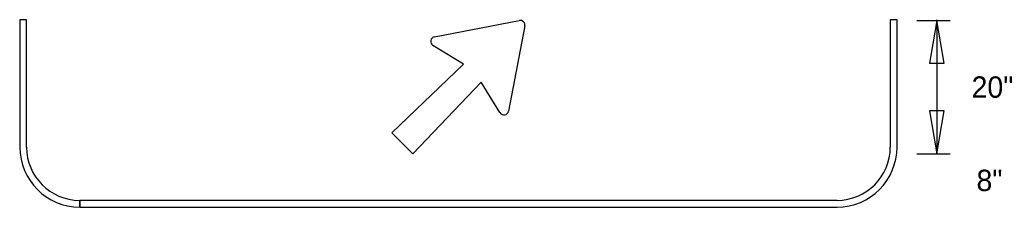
# Model space of a CAD drawing. Extents: x 0 to 770, y 0 to 495.
# Drawn here: x 564.2 to 727.2, y 238.5 to 269.1 of the extents above; entities that cross this region are included whole.
import ezdxf

# ---------------------------------------------------------------- set-up
doc = ezdxf.new("R2010")
doc.units = 0
for name, color, linetype in [('Default', 7, 'Continuous'), ('Dimension', 7, 'Continuous'), ('GSBWFill', 7, 'Continuous'), ('GSColorFill', 7, 'Continuous'), ('GSDims', 7, 'Continuous'), ('GSOutline', 7, 'Continuous')]:
    doc.layers.add(name, color=color, linetype=linetype)

msp = doc.modelspace()

# ---------------------------------------------------------------- linework, layer by layer
at = {"layer": 'Dimension'}
for points in [[(714.87, 269.05), (713.68, 262.04), (716.06, 262.04)], [(714.87, 247.19), (716.06, 254.21), (713.68, 254.21)]]:
    msp.add_lwpolyline(points, close=True, dxfattribs=at)
at = {"layer": 'GSBWFill'}
for p, q in [((564.19, 269.13), (564.19, 248.29)), ((564.19, 269.13), (564.19, 248.29)), ((565.28, 248.29), (565.28, 269.13)), ((632.33, 266.36), (646.26, 269.04)), ((707.22, 269.13), (707.22, 248.29)), ((708.32, 248.29), (708.32, 269.13)), ((708.32, 248.29), (708.32, 269.13)), ((647.17, 268.14), (644.49, 254.2)), ((644.49, 254.2), (644.49, 254.2)), ((574.02, 238.46), (574.02, 239.55)), ((574.02, 238.46), (698.49, 238.46)), ((698.49, 239.55), (574.03, 239.55)), ((574.03, 239.55), (574.03, 238.46)), ((574.03, 238.46), (698.49, 238.46))]:
    msp.add_line(p, q, dxfattribs=at)
for points in [[(565.28, 269.13), (564.19, 269.13)], [(708.32, 269.13), (707.22, 269.13)], [(643.07, 253.94), (640.01, 258.93), (628.75, 247.19), (625.32, 250.62), (637.06, 261.89), (632.07, 264.94)]]:
    msp.add_lwpolyline(points, dxfattribs=at)
for centre, radius, start, end in [((646.41, 268.28), 0.773, 349.1228, 100.8772), ((632.47, 265.6), 0.773, 100.8772, 238.5281), ((643.73, 254.34), 0.773, 211.4719, 349.1228), ((574.02, 248.29), 9.83, 180, 270), ((574.02, 248.29), 9.83, 180, 270), ((574.02, 248.29), 8.73, 180, 270), ((698.49, 248.29), 8.73, 270, 0), ((698.49, 248.29), 9.83, 270, 0), ((698.49, 248.29), 9.83, 270, 0)]:
    msp.add_arc(centre, radius, start, end, dxfattribs=at)
at = {"layer": 'GSColorFill'}
for p, q in [((632.33, 266.36), (646.26, 269.04)), ((647.17, 268.14), (644.49, 254.2)), ((644.49, 254.2), (644.49, 254.2))]:
    msp.add_line(p, q, dxfattribs=at)
msp.add_lwpolyline([(643.07, 253.94), (640.01, 258.93), (628.75, 247.19), (625.32, 250.62), (637.06, 261.89), (632.07, 264.94)], dxfattribs=at)
for centre, start, end in [((646.41, 268.28), 349.1228, 100.8772), ((632.47, 265.6), 100.8772, 238.5281), ((643.73, 254.34), 211.4719, 349.1228)]:
    msp.add_arc(centre, 0.773, start, end, dxfattribs=at)
at = {"layer": 'GSDims'}
for p, q in [((711.59, 269.05), (717.05, 269.05)), ((711.59, 269.05), (717.05, 269.05)), ((714.87, 269.05), (714.87, 269.13)), ((714.87, 269.05), (714.87, 247.19)), ((711.59, 247.19), (717.05, 247.19)), ((711.59, 247.19), (717.05, 247.19))]:
    msp.add_line(p, q, dxfattribs=at)
for points in [[(714.85, 269.13), (714.88, 269.13)], [(714.88, 269.13), (714.87, 269.05), (714.85, 269.13)]]:
    msp.add_lwpolyline(points, dxfattribs=at)
at = {"layer": 'GSOutline'}
for p, q in [((632.33, 266.36), (646.26, 269.04)), ((647.17, 268.14), (644.49, 254.2)), ((644.49, 254.2), (644.49, 254.2))]:
    msp.add_line(p, q, dxfattribs=at)
msp.add_lwpolyline([(643.07, 253.94), (640.01, 258.93), (628.75, 247.19), (625.32, 250.62), (637.06, 261.89), (632.07, 264.94)], dxfattribs=at)
for centre, start, end in [((646.41, 268.28), 349.1228, 100.8772), ((632.47, 265.6), 100.8772, 238.5281), ((643.73, 254.34), 211.4719, 349.1228)]:
    msp.add_arc(centre, 0.773, start, end, dxfattribs=at)

# ---------------------------------------------------------------- texts
at = {"layer": 'Default'}
for s, p in [('20"', (720.57, 256.37)), ('8"', (721.38, 241.08))]:
    msp.add_text(s, height=3.5, dxfattribs=at).set_placement(p)

doc.saveas('drawing.dxf')
